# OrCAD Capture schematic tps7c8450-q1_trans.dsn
size A; title: TPS7C84-Q1 150-mA, 40-V; rev: 1.0; note: SBVS151E –DECEMBER 2010–REVISED MAY 2015
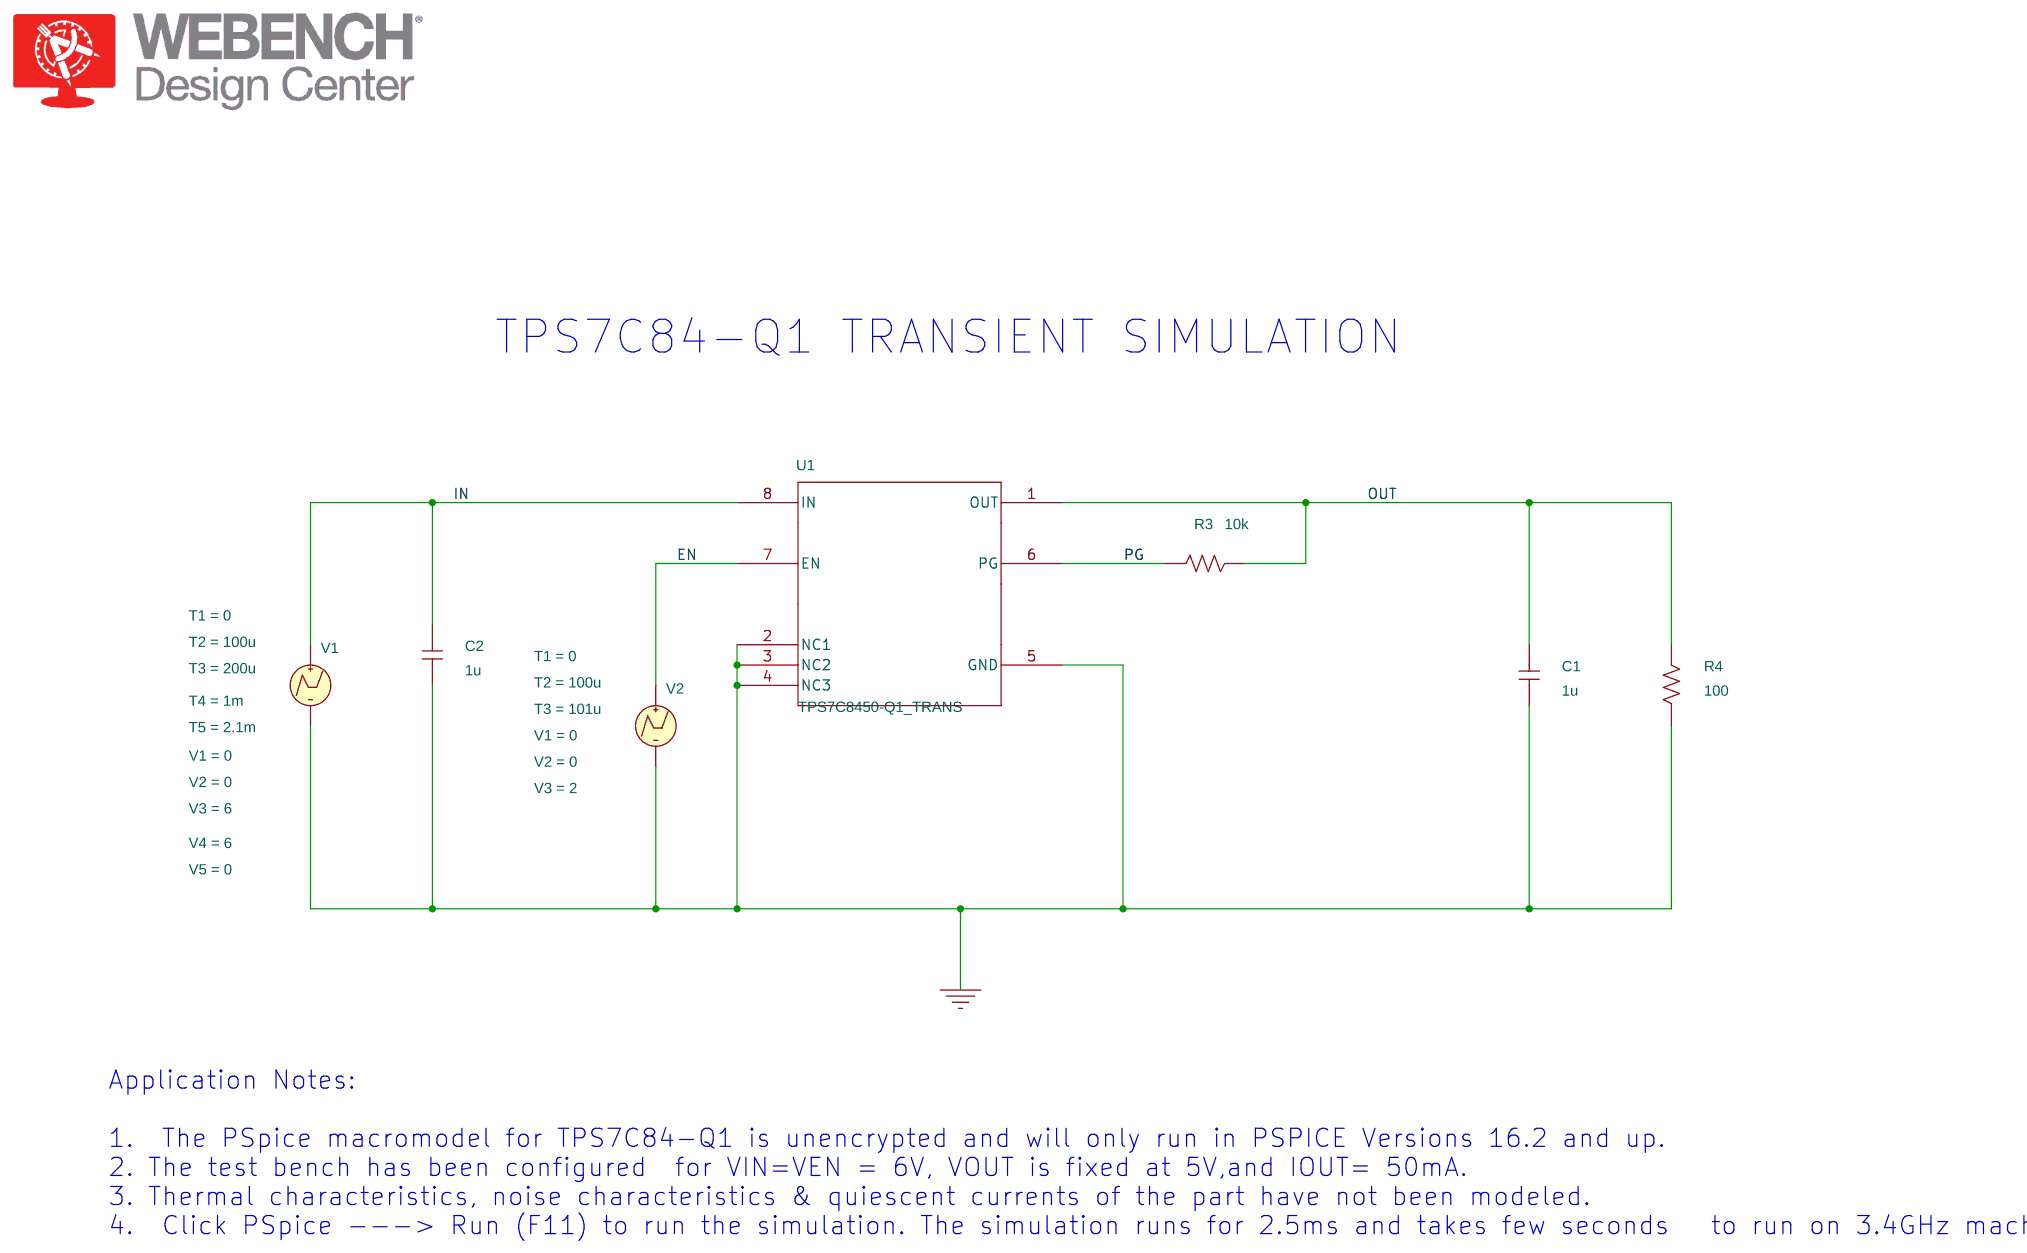
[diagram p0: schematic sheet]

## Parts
C1  1u  [RAD/CK05]
C2  1u  [RAD/CK05]
R3  10k  [AXRC05]
R4  100  [AXRC05]
U1  TPS7C8450-Q1_TRANS  [DBV0005A_N]
V1  VPWL
V2  VPWL

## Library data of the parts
C1 C2 = C
R3 R4 = R
U1 = TPS7C8450-Q1_TRANS
V1 = VPWL: PSpiceTemplate: V^@REFDES %+ %- ?DC|DC @DC| ?AC|AC @AC|\n+PWL @T1 @V1 @T2 @V2 #T3/@T3 @V3/ #T4/@T4 @V4/ #T5/@T5 @V5/ #T6/@T6 @V6/ #T7/@T7 @V7/ #T8/@T8 @V8/ #T9/@T9 @V9/ #T10/@T10 @V10/; T1: 0; T2: 100u; T3: 200u; T4: 1m; T5: 2.1m; V1: 0; V2: 0; V3: 6; V4: 6; V5: 0
V2 = VPWL: PSpiceTemplate: V^@REFDES %+ %- ?DC|DC @DC| ?AC|AC @AC|\n+PWL @T1 @V1 @T2 @V2 #T3/@T3 @V3/ #T4/@T4 @V4/ #T5/@T5 @V5/ #T6/@T6 @V6/ #T7/@T7 @V7/ #T8/@T8 @V8/ #T9/@T9 @V9/ #T10/@T10 @V10/; T1: 0; T2: 100u; T3: 101u; V1: 0; V2: 0; V3: 2

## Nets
0: C1.1 C2.1 R4.1 U1.2(NC1) U1.3(NC2) U1.4(NC3) U1.5(GND) V1.2(-) V2.2(-)
EN: U1.7(EN) V2.1(+)
IN: C2.2 U1.8(IN) V1.1(+)
OUT: C1.2 R3.2 R4.2 U1.1(OUT)
PG: R3.1 U1.6(PG)

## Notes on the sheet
- TPS7C84-Q1 TRANSIENT SIMULATION
- Application Notes:
  1.  The PSpice macromodel for TPS7C84-Q1 is unencrypted and will only run in PSPICE Versions 16.2 and up.
  2. The test bench has been configured  for VIN=VEN = 6V, VOUT is fixed at 5V,and IOUT= 50mA.
  3. Thermal characteristics, noise characteristics & quiescent currents of the part have not been modeled.
  4.  Click PSpice ---> Run (F11) to run the simulation. The simulation runs for 2.5ms and takes few seconds   to run on 3.4GHz machine.
